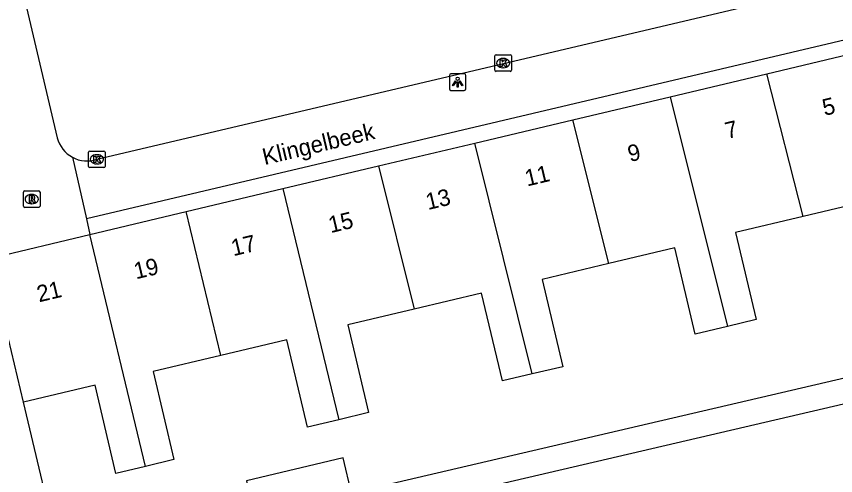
# Model space of a CAD drawing. Extents: x 158038 to 159242, y 380133 to 381214.
# Drawn here: x 158544.2 to 158593.7, y 380904.1 to 380931.84 of the extents above; entities that cross this region are included whole.
import ezdxf

# ---------------------------------------------------------------- set-up
doc = ezdxf.new("R2010")
doc.units = 0
for name, color, linetype in [('IMGEO_Kolk', 7, 'Continuous'), ('IMGEO_Lichtpunt', 7, 'Continuous'), ('IMGEO_Openbare_ruimte_label', 7, 'Continuous'), ('IMGEO_Pand', 7, 'Continuous'), ('IMGEO_Pand_nummerreeks', 7, 'Continuous'), ('IMGEO_Rioolput', 7, 'Continuous'), ('IMGEO_Voetpad_open', 7, 'Continuous')]:
    doc.layers.add(name, color=color, linetype=linetype)

msp = doc.modelspace()

# ---------------------------------------------------------------- linework, layer by layer
at = {"layer": 'IMGEO_Kolk'}
for p, q in [((158573.114, 380928.593), (158573.114, 380929.445)), ((158573.189, 380929.519), (158574.041, 380929.519)), ((158573.602, 380929.299), (158573.627, 380929.299)), ((158574.115, 380929.445), (158574.115, 380928.593)), ((158573.625, 380928.739), (158573.6, 380928.739)), ((158574.041, 380928.519), (158573.189, 380928.519)), ((158548.637, 380923.704), (158549.489, 380923.704)), ((158548.562, 380922.778), (158548.562, 380923.63)), ((158549.05, 380923.484), (158549.075, 380923.484)), ((158549.563, 380923.63), (158549.563, 380922.778)), ((158549.489, 380922.704), (158548.637, 380922.704)), ((158549.073, 380922.924), (158549.048, 380922.924))]:
    msp.add_line(p, q, dxfattribs=at)
for points in [[(158573.114, 380928.593), (158573.114, 380929.445)], [(158573.189, 380929.519), (158574.041, 380929.519)], [(158573.435, 380929.219), (158573.558, 380929.219), (158573.558, 380929.068), (158573.688, 380929.219), (158573.852, 380929.219), (158573.706, 380929.068), (158573.859, 380928.819), (158573.707, 380928.819), (158573.622, 380928.983), (158573.558, 380928.916), (158573.558, 380928.819), (158573.435, 380928.819), (158573.435, 380929.219)], [(158574.115, 380929.445), (158574.115, 380928.593)], [(158574.041, 380928.519), (158573.189, 380928.519)], [(158548.637, 380923.704), (158549.489, 380923.704)], [(158548.562, 380922.778), (158548.562, 380923.63)], [(158548.883, 380923.404), (158549.006, 380923.404), (158549.006, 380923.253), (158549.136, 380923.404), (158549.3, 380923.404), (158549.154, 380923.253), (158549.307, 380923.004), (158549.155, 380923.004), (158549.07, 380923.168), (158549.006, 380923.101), (158549.006, 380923.004), (158548.883, 380923.004), (158548.883, 380923.404)], [(158549.563, 380923.63), (158549.563, 380922.778)], [(158549.489, 380922.704), (158548.637, 380922.704)]]:
    msp.add_lwpolyline(points, dxfattribs=at)
for centre, start, end in [((158573.191, 380929.443), 91.552, 178.448), ((158573.191, 380929.443), 91.552, 178.448), ((158574.039, 380929.443), 1.552, 88.448), ((158574.039, 380929.443), 1.552, 88.448), ((158573.191, 380928.595), 181.552, 268.448), ((158573.191, 380928.595), 181.552, 268.448), ((158574.039, 380928.595), 271.552, 358.448), ((158574.039, 380928.595), 271.552, 358.448), ((158548.639, 380923.628), 91.552, 178.448), ((158548.639, 380923.628), 91.552, 178.448), ((158549.487, 380923.628), 1.552, 88.448), ((158549.487, 380923.628), 1.552, 88.448), ((158548.639, 380922.78), 181.552, 268.448), ((158548.639, 380922.78), 181.552, 268.448), ((158549.487, 380922.78), 271.552, 358.448), ((158549.487, 380922.78), 271.552, 358.448)]:
    msp.add_arc(centre, 0.0765, start, end, dxfattribs=at)
for centre, major_axis, ratio, start_param, end_param in [((158573.601, 380929.019), (-0.387, 0.002), 0.722429, 4.712389, 7.853982), ((158573.626, 380929.019), (-0.39, 0.002), 0.717154, 1.570796, 4.712389), ((158549.049, 380923.204), (-0.387, 0.002), 0.722429, 4.712389, 7.853982), ((158549.074, 380923.204), (-0.39, 0.002), 0.717154, 1.570796, 4.712389)]:
    msp.add_ellipse(centre, major_axis=major_axis, ratio=ratio, start_param=start_param, end_param=end_param, dxfattribs=at)
at = {"layer": 'IMGEO_Lichtpunt'}
for p, q in [((158570.363, 380928.272), (158570.363, 380927.465)), ((158570.363, 380928.272), (158570.363, 380927.465)), ((158571.265, 380928.367), (158570.457, 380928.367)), ((158571.265, 380928.367), (158570.457, 380928.367)), ((158571.359, 380927.465), (158571.359, 380928.272)), ((158571.359, 380927.465), (158571.359, 380928.272)), ((158570.457, 380927.371), (158571.265, 380927.371)), ((158570.457, 380927.371), (158571.265, 380927.371))]:
    msp.add_line(p, q, dxfattribs=at)
for points in [[(158570.737, 380927.936), (158570.776, 380927.908), (158570.588, 380927.646), (158570.55, 380927.673), (158570.737, 380927.936)], [(158570.839, 380927.888), (158570.886, 380927.888), (158570.886, 380927.566), (158570.839, 380927.566), (158570.839, 380927.888)], [(158570.949, 380927.908), (158570.987, 380927.935), (158571.174, 380927.673), (158571.135, 380927.645), (158570.949, 380927.908)]]:
    msp.add_lwpolyline(points, dxfattribs=at)
msp.add_circle((158570.862, 380928.07), 0.0994, dxfattribs=at)
for centre, start, end in [((158570.457, 380928.272), 90, 180), ((158570.457, 380928.272), 90, 180), ((158571.265, 380928.272), 0, 90), ((158571.265, 380928.272), 0, 90), ((158570.457, 380927.465), 180, 270), ((158570.457, 380927.465), 180, 270), ((158571.265, 380927.465), 270, 0), ((158571.265, 380927.465), 270, 360)]:
    msp.add_arc(centre, 0.0946, start, end, dxfattribs=at)
at = {"layer": 'IMGEO_Pand'}
for points in [[(158589.539, 380928.367), (158595.363, 380929.749)], [(158583.706, 380926.984), (158589.539, 380928.367)], [(158591.746, 380919.752), (158589.539, 380928.367)], [(158577.823, 380925.588), (158583.706, 380926.984)], [(158583.706, 380926.984), (158587.172, 380913.117)], [(158571.902, 380924.184), (158577.823, 380925.588)], [(158580.001, 380916.912), (158577.823, 380925.588)], [(158566.079, 380922.803), (158571.902, 380924.184)], [(158575.365, 380910.242), (158571.902, 380924.184)], [(158560.304, 380921.433), (158566.079, 380922.803)], [(158566.079, 380922.803), (158568.235, 380914.162)], [(158554.451, 380920.044), (158560.304, 380921.433)], [(158560.304, 380921.433), (158563.676, 380907.477)], [(158598.861, 380915.842), (158596.984, 380915.397), (158595.727, 380920.696), (158591.746, 380919.752)], [(158548.627, 380918.663), (158554.451, 380920.044)], [(158556.555, 380911.355), (158554.451, 380920.044)], [(158591.746, 380919.752), (158587.647, 380918.78), (158588.894, 380913.526), (158587.172, 380913.117)], [(158542.764, 380916.371), (158542.562, 380917.224), (158548.627, 380918.663)], [(158551.99, 380904.659), (158548.627, 380918.663)], [(158587.172, 380913.117), (158585.214, 380912.653), (158583.98, 380917.856), (158580.001, 380916.912)], [(158580.001, 380916.912), (158575.965, 380915.955), (158577.216, 380910.681), (158575.365, 380910.242)], [(158544.622, 380908.541), (158543.716, 380912.36), (158542.764, 380916.371)], [(158575.365, 380910.242), (158573.571, 380909.816), (158572.31, 380915.129), (158568.235, 380914.162)], [(158568.235, 380914.162), (158564.224, 380913.211), (158565.482, 380907.905), (158563.676, 380907.477)], [(158563.676, 380907.477), (158561.789, 380907.029), (158560.539, 380912.3), (158556.555, 380911.355)], [(158556.555, 380911.355), (158552.456, 380910.382), (158553.716, 380905.068), (158551.99, 380904.659)], [(158551.99, 380904.659), (158550.213, 380904.237), (158548.949, 380909.567), (158544.622, 380908.541)], [(158564.442, 380903.037), (158563.934, 380905.176), (158558.095, 380903.79), (158558.597, 380901.675)]]:
    msp.add_lwpolyline(points, dxfattribs=at)
at = {"layer": 'IMGEO_Rioolput'}
for p, q in [((158544.624, 380920.377), (158544.624, 380921.229)), ((158544.699, 380921.303), (158545.551, 380921.303)), ((158545.625, 380921.229), (158545.625, 380920.377)), ((158545.112, 380921.083), (158545.137, 380921.083)), ((158545.551, 380920.303), (158544.699, 380920.303)), ((158545.135, 380920.523), (158545.11, 380920.523))]:
    msp.add_line(p, q, dxfattribs=at)
for points in [[(158544.624, 380920.377), (158544.624, 380921.229)], [(158544.699, 380921.303), (158545.551, 380921.303)], [(158545.625, 380921.229), (158545.625, 380920.377)], [(158545.213, 380921.001), (158544.961, 380921.003), (158544.961, 380920.603)], [(158544.961, 380920.603), (158545.085, 380920.603), (158545.085, 380920.765), (158545.096, 380920.765)], [(158545.139, 380920.922), (158545.085, 380920.922), (158545.085, 380920.841)], [(158545.085, 380920.841), (158545.137, 380920.841)], [(158545.143, 380920.736), (158545.214, 380920.603), (158545.354, 380920.603), (158545.289, 380920.729)], [(158545.551, 380920.303), (158544.699, 380920.303)]]:
    msp.add_lwpolyline(points, dxfattribs=at)
for centre, radius, start, end in [((158544.701, 380921.227), 0.0765, 91.552, 178.448), ((158544.701, 380921.227), 0.0765, 91.552, 178.448), ((158545.549, 380921.227), 0.0765, 1.552, 88.448), ((158545.549, 380921.227), 0.0765, 1.552, 88.448), ((158545.095, 380920.712), 0.0533, 26.0293, 88.6989), ((158545.121, 380921.03), 0.19, 274.7715, 282.9687), ((158545.145, 380920.826), 0.0964, 77.0061, 93.1865), ((158545.159, 380920.883), 0.0378, 276.6634, 79.6772), ((158545.212, 380920.891), 0.109, 350.3612, 89.416), ((158545.21, 380920.891), 0.112, 277.5842, 350.9817), ((158545.194, 380920.676), 0.108, 29.5134, 73.7905), ((158544.701, 380920.379), 0.0765, 181.552, 268.448), ((158544.701, 380920.379), 0.0765, 181.552, 268.448), ((158545.549, 380920.379), 0.0765, 271.552, 358.448), ((158545.549, 380920.379), 0.0765, 271.552, 358.448)]:
    msp.add_arc(centre, radius, start, end, dxfattribs=at)
for centre, major_axis, ratio, start_param, end_param in [((158545.111, 380920.803), (-0.387, 0.002), 0.722429, 4.712389, 7.853982), ((158545.136, 380920.803), (-0.39, 0.002), 0.717154, 1.570796, 4.712389)]:
    msp.add_ellipse(centre, major_axis=major_axis, ratio=ratio, start_param=start_param, end_param=end_param, dxfattribs=at)
at = {"layer": 'IMGEO_Voetpad_open'}
for points in [[(158543.181, 380939.237), (158546.669, 380924.5)], [(158609.162, 380933.95), (158548.439, 380919.601)], [(158549.066, 380923.206), (158591.36, 380933.189)], [(158547.585, 380923.329), (158548.439, 380919.601)], [(158548.439, 380919.601), (158548.627, 380918.663)], [(158605.649, 380912.643), (158581.798, 380907.083), (158564.442, 380903.037)], [(158549.679, 380887.047), (158547.216, 380897.489), (158556.488, 380899.652), (158606.012, 380911.202)], [(158558.597, 380901.675), (158546.898, 380898.948), (158544.622, 380908.541)]]:
    msp.add_lwpolyline(points, dxfattribs=at)
for centre, radius, start, end in [((158548.471, 380924.965), 1.861, 194.4873, 241.5804), ((158548.466, 380924.965), 1.858, 241.6859, 288.8189)]:
    msp.add_arc(centre, radius, start, end, dxfattribs=at)

# ---------------------------------------------------------------- texts
at = {"layer": 'IMGEO_Openbare_ruimte_label'}
msp.add_text('Klingelbeek', height=1, rotation=13.3553, dxfattribs=at).set_placement((158559.196, 380922.851))
at = {"layer": 'IMGEO_Pand_nummerreeks'}
for s, p in [('5', (158593.032, 380925.825)), ('7', (158587.152, 380924.43)), ('9', (158581.272, 380923.036)), ('11', (158575.056, 380921.561)), ('13', (158569.065, 380920.139)), ('15', (158563.185, 380918.744)), ('17', (158557.305, 380917.349)), ('19', (158551.424, 380915.955)), ('21', (158545.565, 380914.565))]:
    msp.add_text(s, height=1, rotation=13.3445, dxfattribs=at).set_placement(p)

doc.saveas('drawing.dxf')
